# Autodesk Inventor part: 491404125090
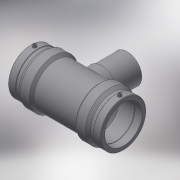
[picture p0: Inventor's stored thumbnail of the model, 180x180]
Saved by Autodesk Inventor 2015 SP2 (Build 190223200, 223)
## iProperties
Created: 2017-06
Part Number: 491404125090
Material: Generic
Description: PLASSON REDUCING TEE 125x90x125
Document SubType Name: Modeling
Designer: KIM
Mass: 3050.17 g
Surface Area: 3911.36 cm^2
Volume: 3050.17 cm^3
Density: 1 g/cm^3
Appearance: Default
Author: KIM
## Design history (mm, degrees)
derived "491404.ipt"
feature "Solid1::491404.ipt"
tag "TaggingFeature1"
body "Solid1"
other parameters: "d0" = 382, "d1" = 125, "d2" = 165, "d3" = 86, "d4" = 76.4, "d5" = 148.5, "d6" = 118.75, "d7" = 125, "d8" = 168 deg, "d10" = 34.4, "d11" = 11.46667, "d13" = 382, "d14" = 17.6296, "d17" = 112.5, "d18" = 125, "d19" = 3.52592, "d20" = 168 deg, "d22" = 153.45, "d23" = 165, "d25" = 135 deg, "d26" = 267.4, "d29" = 88, "d30" = 15, "d31" = 152.8, "d34" = 5 deg, "d35" = 15, "d39" = 5 deg, "d41" = 4, "d42" = 14, "d43" = 0, "d45" = 4, "d46" = 6, "d47" = 0, "d48" = -161, "d51" = 0, "d52" = 72, "d54" = 0, "d55" = 148.5, "d56" = 165, "d57" = 133.7, "d58" = 135 deg, "d59" = 86, "d60" = 86, "d61" = 135 deg, "d62" = 161, "d72" = 173.81, "d73" = 86.905, "d74" = -161, "d75" = 94.5, "d77" = 0, "d78" = 72, "d80" = 0, "d82" = 78.5, "d83" = 0, "d84" = 3, "d85" = 0, "d86" = 28.66667, "d87" = 150.381, "d88" = 11.46667, "d89" = 3, "d90" = 0, "d_" = 125, "L_" = 382, "L_1" = 86, "D_" = 165, "A_" = 88, "d_2" = 12, "H_" = 161
